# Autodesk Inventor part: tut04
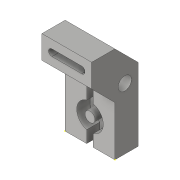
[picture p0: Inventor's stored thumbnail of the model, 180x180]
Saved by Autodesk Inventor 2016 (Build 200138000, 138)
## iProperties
Created: 2015-03
Part Number: tut04
Material: Generic
Document SubType Name: Modeling
Designer: Sandeep
Density: 1 g/cm^3
Appearance: Default
Author: Sandeep
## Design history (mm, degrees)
sketch "Sketch1"
  geometry: L1 (0, 0)-(0, 30); L2 (0, 30)-(-14, 44); L3 (-14, 44)-(-14, 58); L4 (-14, 58)-(0, 58); L5 (14, 44)-(14, 0); L6 (14, 0)-(0, 0); L7 (0, 58)-(14, 44)
  constraints: 14 end point, 3 parallel, 1 horizontal, 1 perpendicular, 1 vertical
  dimensions: "d0" = 14 distance between parallel lines of L5 L1; "d1" = 14 distance from line of L4.end L5; "d2" = 14 horizontal distance of L4.end L5.start; "d3" = 28 distance between parallel lines of L3 L5; "d4" = 58 distance between parallel lines of L4 L6; "d5" = 14 distance of L2.end L3.end
extrude "Extrusion1" new body sketch "Sketch1" distance "d6" = 30; taper "d7" = 0 deg
sketch "Sketch2"
  geometry: 1 further point
hole "Hole1" diameter "d10" = 8; stored, may be unused: countersink angle "d14" = 90 deg, drill point angle "d16" = 118 deg; dims "d8" = 21, "d9" = 8, "d11" = 6, "d12" = 4, "d13" = 2, "d15" = 8
sketch "Sketch3"
  geometry: L1 (0, 0)-(30, 0) reference; L2 (0, -30)-(30, -30) reference; L3 (30, 0)-(30, -30) reference; L4 (13, 0)-(13, -7.254); L5 (0, 3)-(30, 3) reference; L6 (17, 0)-(17, -7.254); L7 (15, -15)-(15, 7.075); L8 (13, 0)-(17, 0); L9 (-6.754, -15)-(33.848, -15); L10 (13, -22.746)-(13, -30); L11 (17, -30)-(17, -22.746); C1 r 3 at (15, -15); A1 r 8 centre (15, -15) between (13, -7.254) and (13, -22.746); A2 r 8 centre (15, -15) between (17, -22.746) and (17, -7.254)
  constraints: 14 end point, 5 point on line, 4 point on circle, 3 centre point, 2 parallel, 2 perpendicular, 1 coincident, 1 collinear, 1 horizontal, 1 vertical, 2 other
  dimensions: "d19" = 6 diameter of C1; "d21" = 15 distance from line of L2 A1.centre; "d22" = 15 distance from line of A1.centre L3; "d23" = 4 distance between parallel lines of L6 L4; "d24" = 4 distance between parallel lines of L11 L10; "d25" = 8 radius of A2; "d26" = 8 radius of A1
sketch "Sketch4"
  geometry: 1 further point
extrude "Extrusion2" cut sketch "Sketch3" distance "d27" = 8; taper "d28" = 0 deg
sketch "Sketch5"
  geometry: L1 (6, 7)-(24, 7); L2 (6, 5)-(24, 5); L3 (24, 9)-(6, 9); L4 (0, 14)-(30, 14) reference; L5 (30, 0)-(30, 14) reference; A1 r 2 centre (6, 7) between (6, 9) and (6, 5); A2 r 2 centre (24, 7) between (24, 5) and (24, 9); 2 further points
  constraints: 8 end point, 4 point on circle, 4 tangent, 2 centre point, 1 horizontal, 1 midpoint, 1 parallel
  dimensions: "d29" = 7 distance between parallel lines of L4 L1; "d30" = 18 distance of L1.start L1.end; "d31" = 6 distance from line of L5 L1.end; "d32" = 2 radius of A2
extrude "Extrusion3" cut sketch "Sketch5" distance "d33" = 11; taper "d34" = 0 deg
body "Solid1"
other parameters: "d20" = 16
